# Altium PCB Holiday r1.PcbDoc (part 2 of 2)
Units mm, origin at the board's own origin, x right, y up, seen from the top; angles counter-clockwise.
Board outline 67 x 67 mm, 4 copper layers (Top Layer, Mid-Layer 1, InternalPlane1, Bottom Layer), stack 1.602 mm thick; 125 components, 139 nets, 622 pads, 401 vias.
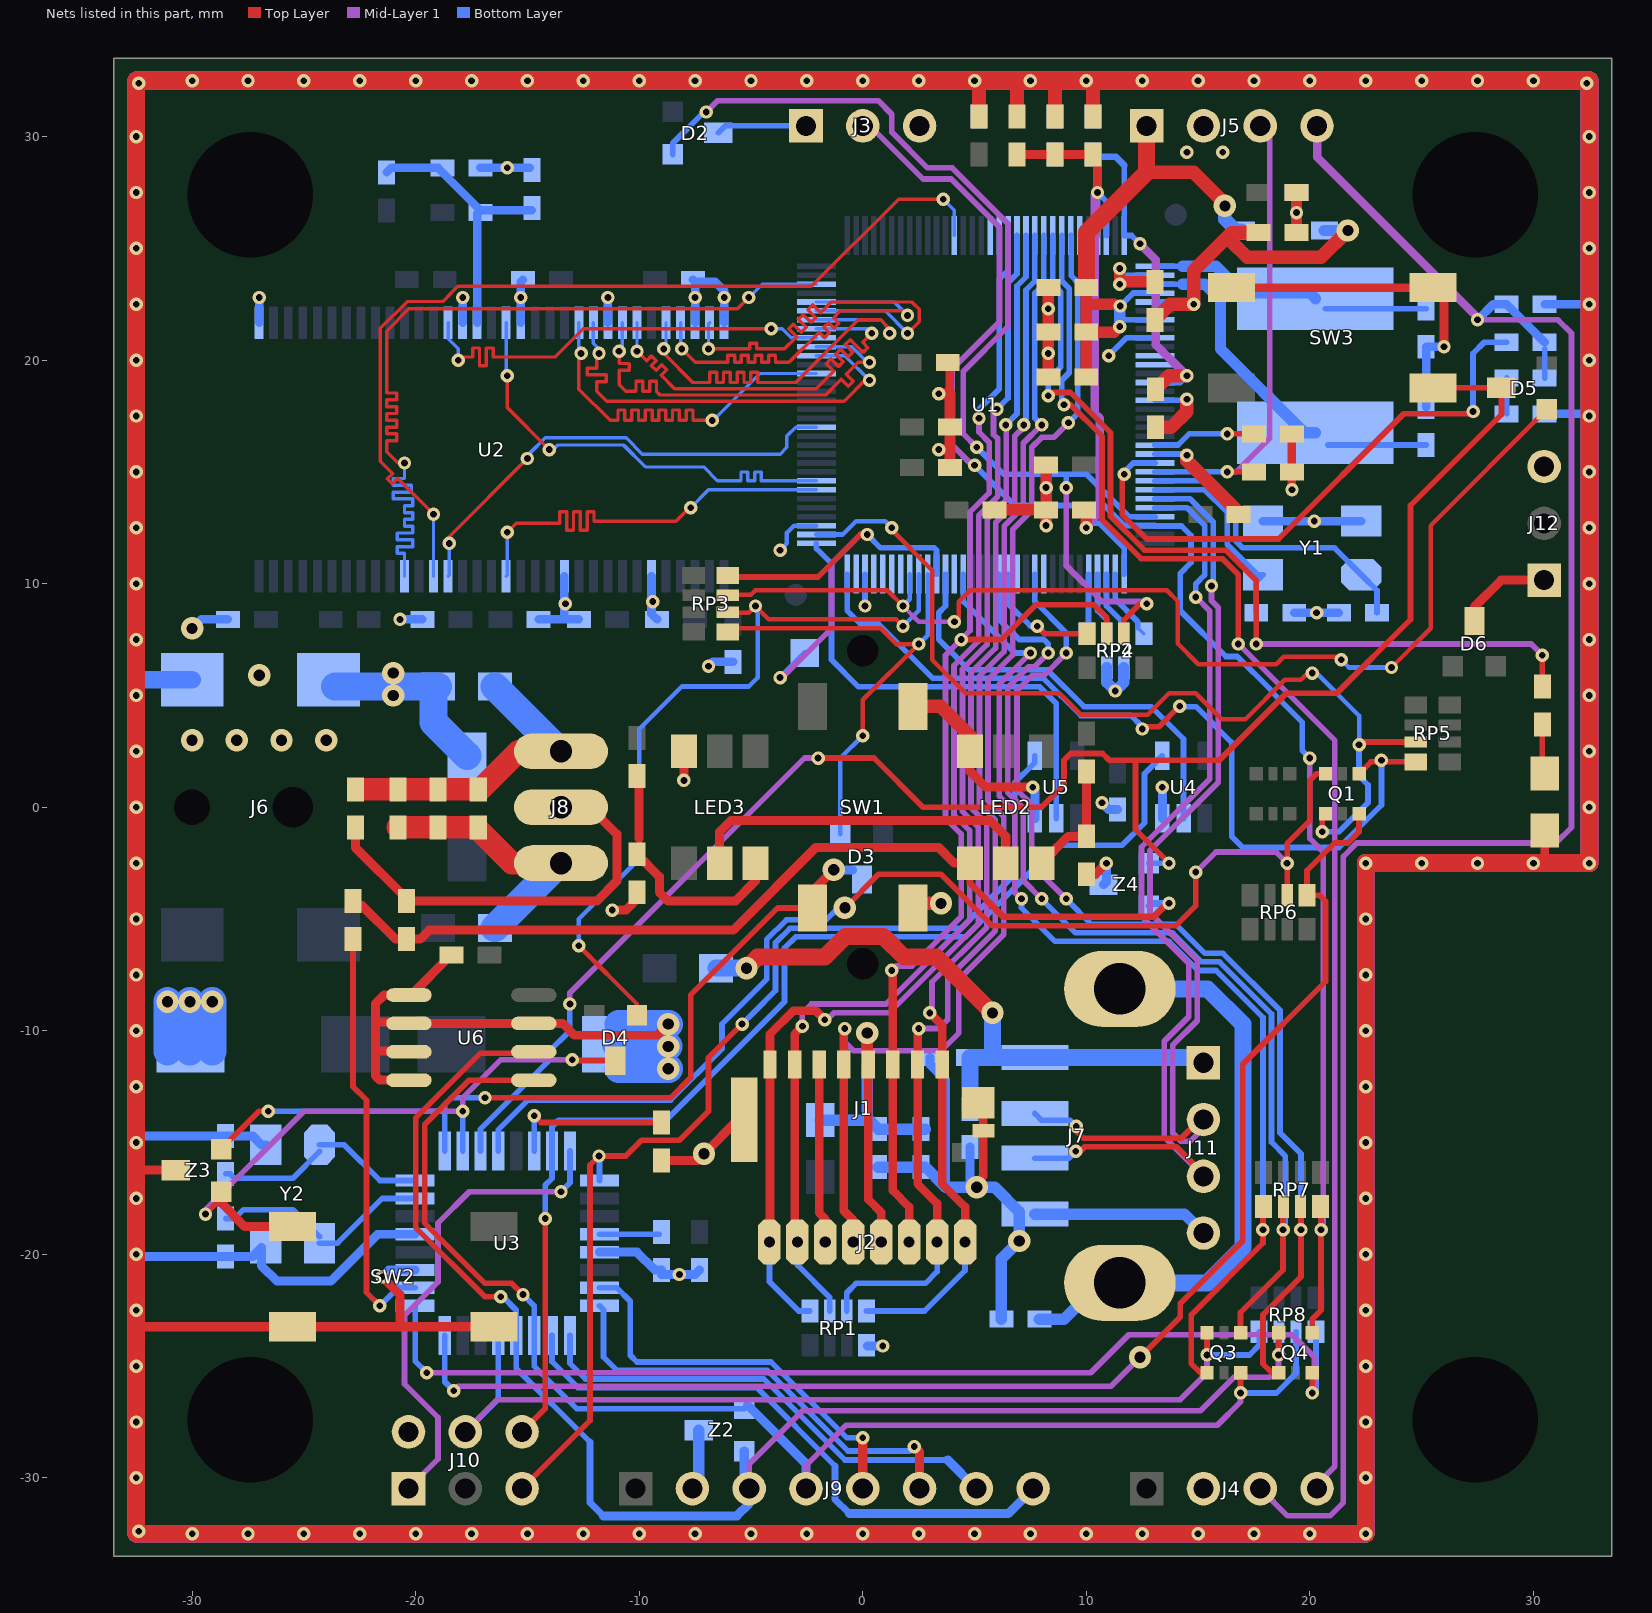
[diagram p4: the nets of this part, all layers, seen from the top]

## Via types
v1: diameter 0.6, hole 0.3, Top Layer to Bottom Layer, tented both sides, 365 vias
v2: diameter 1, hole 0.5, Top Layer to Bottom Layer, tented both sides, 33 vias
v3: diameter 0.6, hole 0.3, Top Layer to Bottom Layer, 2 vias
v4: diameter 0.9, hole 0.5, Top Layer to Bottom Layer, tented both sides, 1 vias

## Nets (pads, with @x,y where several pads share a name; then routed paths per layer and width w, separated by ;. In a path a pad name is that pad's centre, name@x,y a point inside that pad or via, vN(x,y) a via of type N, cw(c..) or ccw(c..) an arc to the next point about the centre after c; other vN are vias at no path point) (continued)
D9: U1.52 U2.56 | length 20.9
  Top Layer w0.152: v1(-12.6,20.3) -12.7,20.3 -12.7,18.7 -11.303,17.303 -10.948,17.303 -10.948,17.77 -10.643,17.77 -10.643,17.303 -10.338,17.303 -10.338,17.77 -10.033,17.77 -10.033,17.303 -9.728,17.303 -9.728,17.77 -9.424,17.77 -9.424,17.303 -9.119,17.303 -9.119,17.77 -8.814,17.77 -8.814,17.303 -8.509,17.303 -8.509,17.77 -8.204,17.77 -8.204,17.303 -7.9,17.303 -7.9,17.77 -7.595,17.77 -7.595,17.303 v1(-6.727,17.303)
  Bottom Layer w0.152: U2.56@-12.7,21.675 -12.7,20.5 -12.75,20.45 -12.8,20.4 -12.7,20.3 v1(-12.6,20.3) ; v1(-6.727,17.303) -6.697,17.303 -4.6,19.4 U1.52@-2.075,19.4
D10: U1.54 U2.57 | length 21
  Top Layer w0.152: v1(-11.8,20.3) -11.7,20.3 -11.75,20.25 -11.9,20.1 -11.9,19.643 -12.332,19.643 -12.332,19.338 -11.468,19.338 -11.468,19.033 -11.9,19.033 -11.9,18.6 -11.462,18.162 -0.838,18.162 v1@0.1,19.1
  Mid-Layer 1 w0.152: v1@0.1,19.1 v1(0.3,19.1)
  Bottom Layer w0.152: U2.57@-12.05,21.675 -12.05,20.75 -11.7,20.4 -11.7,20.3 -11.7,20.2 v1(-11.8,20.3) ; U1.54@-2.075,20.2 -0.8,20.2 v1(0.3,19.1)
D11: U1.55 U2.59 | length 20.9
  Top Layer w0.152: v1(-10.9,20.4) -10.9,19.848 -10.444,19.848 -10.444,19.543 -10.9,19.543 -10.9,18.9 -10.6,18.6 -10.143,18.6 -10.143,19.056 -9.838,19.056 -9.838,18.6 -9.533,18.6 -9.533,19.056 -9.228,19.056 -9.228,18.6 -9.07,18.441 -1.659,18.441 -0.954,19.146 -0.648,18.84 -0.433,19.055 -0.739,19.361 -0.2,19.9 v1(0.3,19.9)
  Bottom Layer w0.152: v1(-10.9,20.4) -10.75,20.55 U2.59@-10.75,21.675 ; U1.55@-2.075,20.6 -0.5,20.6 v1@0.15,19.95
D12: U1.57 U2.60 | length 20.9
  Top Layer w0.152: v1(-10.1,20.4) -9.67,19.97 -9.454,20.185 -9.239,19.97 -9.454,19.754 -9.239,19.539 -8.987,19.79 -8.772,19.575 -9.023,19.323 -8.421,18.721 -2.079,18.721 -1.301,19.499 -1.642,19.841 -1.427,20.056 -1.085,19.715 -0.87,19.93 -1.211,20.272 -0.996,20.487 -0.654,20.146 -0.439,20.361 -0.78,20.703 -0.565,20.918 -0.223,20.577 0.012,20.342 0.227,20.557 -0.008,20.792 v1(0.4,21.2)
  Bottom Layer w0.152: v1(-10.1,20.4) U2.60@-10.1,21.675 ; U1.57@-2.075,21.4 0.2,21.4 v1(0.4,21.2)
D13: U1.58 U2.62 | length 20.9
  Top Layer w0.152: v1(-8.9,20.5) -8.9,20.3 -7.6,19 -6.838,19 -6.838,19.451 -6.533,19.451 -6.533,19 -6.228,19 -6.228,19.451 -5.924,19.451 -5.924,19 -5.619,19 -5.619,19.451 -5.314,19.451 -5.314,19 -5.009,19 -5.009,19.451 -4.704,19.451 -4.704,19 -3,19 -0.2,21.8 0.8,21.8 1.104,21.496 1.104,21.2 v1(1.2,21.2)
  Bottom Layer w0.152: v1(-8.9,20.5) -8.8,20.6 U2.62@-8.8,21.675 ; U1.58@-2.075,21.8 0.8,21.8 1.104,21.496 1.104,21.2 v1(1.2,21.2)
D14: U1.60 U2.63 | length 20.9
  Top Layer w0.152: v1(-8.1,20.5) -7.5,19.9 -6.038,19.9 -6.038,20.221 -5.733,20.221 -5.733,19.9 -5.428,19.9 -5.428,20.221 -5.124,20.221 -5.124,19.9 -4.819,19.9 -4.819,20.221 -4.514,20.221 -4.514,19.9 -4.209,19.9 -4.209,20.221 -3.904,20.221 -3.904,19.9 -3.3,19.9 -1.954,21.246 -1.712,21.003 -1.496,21.219 -1.739,21.461 -1.523,21.677 -1.281,21.434 -1.065,21.65 -1.308,21.892 -1,22.2 1.8,22.2 v1(2,22)
  Bottom Layer w0.152: U2.63@-8.15,21.675 -8.15,20.5 -8.15,20.45 v1(-8.1,20.5) ; U1.60@-2.075,22.6 1.4,22.6 v1(2,22)
D15: U1.59 U2.65 | length 21.1
  Top Layer w0.152: v1(-6.9,20.5) -5.048,20.5 -5.048,20.754 -4.743,20.754 -4.743,20.5 -3.5,20.5 -2.961,21.039 -3.32,21.398 -3.105,21.614 -2.746,21.254 -2.53,21.47 -2.883,21.822 -2.667,22.038 -2.315,21.685 -2.099,21.901 -2.452,22.253 -2.236,22.469 -1.884,22.116 -1.4,22.6 2.2,22.6 2.525,22.275 2.525,21.725 v1(2,21.2) v1@1.9,21.3
  Bottom Layer w0.152: v1(-6.9,20.5) -6.9,21.625 U2.65@-6.85,21.675 ; U1.59@-2.075,22.2 1,22.2 v1(2,21.2)
D_RXD: D2.1 RP4.2.1 U1.125 | length 49.9
  Top Layer w0.254: v1@9,14.2 v1(9.1,14.3) ; RP4.2.1@11.681,7.762 11.681,8.381 12.4,9.1 v1(12.7,9.1)
  Mid-Layer 1 w0.254: v1(-7,31.1) -6.5,31.6 0.7,31.6 1.3,31 1.3,30.2 2.9,28.6 4,28.6 6.5,26.1 6.5,21.5 4.5,19.5 4.5,16.7 v1(5.1,16.1) ; v1(9.1,14.3) 9.1,10.8 10.7,9.2 12.6,9.2 v1(12.7,9.1)
  Bottom Layer w0.254: D2.1@-8.5,29.2 -8.5,29.7 -7.1,31.1 v1(-7,31.1) ; v1(5.1,16.1) 6.3,14.9 9.1,14.9 ; v1(9.1,14.3) 9.1,14.9 ; U1.125@13.075,13 11.9,13 10,14.9 9.1,14.9
D_TXD: J3.2 Q4.1 RP7.4.1 U1.126 | length 71
  Top Layer w0.254: Q4.1@20.1,-23.5 20.1,-22.9 20.5,-22.5 v1(20.5,-18.9) 20.5,-17.892 RP7.4.1@20.47,-17.862
  Mid-Layer 1 w0.254: J3.2@0,30.48 0.32,30.48 2.7,28.1 3.961,28.1 6.119,25.942 6.119,21.719 4,19.6 4,16.2 4.9,15.3 v1(5,15.3) ; v1(20,2.2) 20,-1.4 20.6,-2 20.6,-18.8 v1(20.5,-18.9)
  Bottom Layer w0.254: v1(5,15.3) 6.8,13.5 10.8,13.5 11.7,12.6 U1.126@13.075,12.6 13.094,12.581 14.258,12.581 14.681,12.158 14.681,10.942 14.199,10.46 14.199,8.788 16.241,6.746 16.754,6.746 18.281,5.219 18.281,5.181 19.654,3.807 19.654,2.546 v1(20,2.2)
D_TXD_5V: Q4.6 RP8.1.1 U3.1 | length 49.4
  Top Layer w0.254: v1(20.1,-26.2) Q4.6@20.1,-25.3
  Mid-Layer 1 w0.254: v1(-19.5,-25.3) 10.2,-25.3 11.9,-23.6 19.2,-23.6 20.2,-24.6 20.2,-26 v1@20.05,-26.15
  Bottom Layer w0.254: U3.1@-20.025,-22.3 -20.025,-24.775 v1(-19.5,-25.3) ; v1(20.1,-26.2) 20.27,-26.03 RP8.1.1@20.27,-23.462
DEBUG: J4.4 U1.89 | length 64
  Top Layer w0.254: v1(9,18) 9.3,18 10.7,16.6 10.7,12.861 12.442,11.119 16.081,11.119 16.8,10.4 v1(16.8,7.3)
  Mid-Layer 1 w0.254: v1(16.8,7.3) 21.119,2.981 21.119,-29.481 20.32,-30.28 J4.4@20.32,-30.48
  Bottom Layer w0.254: U1.89@8.9,25.575 8.9,23.539 9.235,23.204 9.235,19.435 8.9,19.1 8.9,18.1 v1(9,18)
DOUT: R9.2 U3.2 | length 18.8
  Top Layer w0.254: R9.2@-22.8,-5.9 -22.8,-12.5 -22.2,-13.1 -22.2,-21.7 v1(-21.6,-22.3)
  Bottom Layer w0.254: v1(-21.6,-22.3) -20.8,-21.5 U3.2@-20.025,-21.5
DOUT2: L6.1 LED2.1 R9.1 Z4.2 | length 41.7
  Top Layer w0.305: LED2.1@4.8,-2.5 4.8,-3.4 6.3,-4.9 13,-4.9 v1@13.6,-4.3
  Top Layer w0.406: R9.1@-22.8,-4.4 -22.4,-4.4 -20.9,-5.9 L6.1@-20.4,-5.9 -19.8,-5.9 -19.4,-5.5 -5.8,-5.5 -2.1,-1.8 3.4,-1.8 4.1,-2.5 LED2.1@4.8,-2.5
  Bottom Layer w0.305: Z4.2@12.8,-4.405 12.905,-4.3 v1(13.7,-4.3)
DQM0: U1.46 U2.20 | length 21
  Top Layer w0.152: v1(-18.5,11.8) -18.5,12.1 v1(-15,15.6)
  Bottom Layer w0.152: U2.20@-18.55,10.325 -18.5,10.375 v1(-18.5,11.8) ; v1@-14.931,15.8 -14.21,16.521 -10.579,16.521 -9.856,15.797 -3.692,15.797 -3.394,16.094 -3.394,16.606 -3,17 U1.46@-2.075,17
DQM1: U1.56 U2.47 | length 21
  Top Layer w0.152: v1@-18.1,20.141 -17.448,20.141 -17.448,20.541 -17.143,20.541 -17.143,19.742 -16.838,19.742 -16.838,20.541 -16.533,20.541 -16.533,20.141 -13.759,20.141 -12.5,21.4 v1(-4.1,21.4)
  Bottom Layer w0.152: U2.47@-18.55,21.675 -18.55,20.95 -18.1,20.5 v1(-18.1,20) ; v1(-4.1,21.4) -3.6,21.4 -3.2,21 U1.56@-2.075,21
DQS0: U1.39 U2.16 | length 21.2
  Top Layer w0.152: v1(-15.9,12.3) -15.5,12.7 -13.548,12.7 -13.548,13.216 -13.243,13.216 -13.243,12.384 -12.938,12.384 -12.938,13.216 -12.633,13.216 -12.633,12.384 -12.328,12.384 -12.328,13.216 -12.024,13.216 -12.024,12.8 -8.354,12.8 -7.727,13.427 v1@-7.624,13.53
  Mid-Layer 1 w0.152: v1(-7.7,13.4) -7.624,13.4 v1@-7.624,13.53
  Bottom Layer w0.152: U2.16@-15.95,10.325 -15.9,10.375 v1(-15.9,12.3) ; v1(-7.7,13.4) -6.9,14.2 U1.39@-2.075,14.2
DQS1: U1.40 U2.51 | length 20.9
  Top Layer w0.152: v1(-15.9,19.3) -15.9,17.881 v1(-14.019,16) v1@-13.838,16
  Bottom Layer w0.152: U2.51@-15.95,21.675 -15.95,19.35 v1(-15.9,19.3) ; v1(-14.019,16) -13.838,16 -13.635,16.203 -10.703,16.203 -9.721,15.221 -7.121,15.221 -6.5,14.6 -5.448,14.6 -5.448,14.994 -5.143,14.994 -5.143,14.6 -4.838,14.6 -4.838,14.994 -4.533,14.994 -4.533,14.6 U1.40@-2.075,14.6
GND: C1.2 C2.2 C3.2 C4.2 C5.2 C6.2 C7.2 C8.2 C9.2 C10.2 C11.2 C12.2 C13.2 C14.2 C15.2 C16.2 C17.2 C18.2 C19.2 C20.2 C21.2 C22.2 C23.2 C24.2 C25.2 C26.2 C27.2 C28.2 C29.2 C30.2 C31.2 C32.2 C33.2 C35.2 C36.2 C37.2 C38.2 C39.2 C40.2 C41.2 C42.2 C43.2 C44.2 C45.2 C46.2 C48.2 C49.1 C50.2 C51.2 C55.1 C56.1 C57.2 J1.6 J1.G1 J1.G2 J1.G3 J2.6 J3.3 J4.2 J5.2 J6.2 J6.3 J7.4 J9.2 J10.6 J11.4 J12.3 L4.1 L7.1 LED1.K LED2.6 LED3.6 pad.0@27.4,27.4 pad.0@-27.4,27.4 pad.0@-27.4,-27.4 R5.2 R7.1 R12.1 RP1.4.2 RP2.2.2 RP2.3.2 SW1.3 SW1.4 SW2.3 SW2.4 SW3.3 SW3.4 U1.30 U1.35 U1.98 U1.105 U1.112 U1.118 U2.6 U2.12 U2.34 U2.48 U2.52 U2.58 U2.64 U2.66 U3.3 U3.5 U3.21 U4.3 U5.3 U6.1 U6.2 U6.3 U6.4 U6.7 Y1.3 Y1.4 Y2.3 Y2.4 Z1.1 Z2.3 Z3.3 Z4.3 | length 1042.6
  Top Layer w0.254: v1(11.5,23.4) v1@11.6,23.5
  Top Layer w0.381: J1.6@-1.95,-11.5 -1.95,-18.15 -1.675,-18.425 ; 3.9,18.5 C6.2@3.9,20 ; v2(5.1,-17) 5.1,-16.8 5.4,-16.5 J1.G3@5.4,-14.475 5.4,-13.45 J1.G2@5.175,-13.225 ; SW3.4@16.49,23.24 SW3.3@25.51,23.24 26,22.75 v1(26,20.6) ; v1(19.2,14.2) C31.2@19.2,15 C37.2@19.2,16.7 ; 30.5,-2.5 LED1.K@30.5,-1.04
  Top Layer w0.4: v1(-21.5,-21) -20.7,-21.8 -20.7,-23.24 ; U6.2@-20.37,-9.6 U6.2@-20.3,-9.67 U6.7@-14.712,-9.67 -13.43,-9.67 -12.9,-10.2 -9.2,-10.2 v2(-8.7,-9.7)
  Top Layer w0.406: -32.5,-16.3 -32.435,-16.235 Z3.3@-30.732,-16.235 ; -32.44,-23.24 SW2.3@-25.51,-23.24 -20.7,-23.24 SW2.4@-16.49,-23.24 ; U6.2@-20.37,-9.6 -21.8,-9.6 ; U6.3@-20.34,-10.9 -21.8,-10.9 ; U6.4@-20.3,-12.21 -20.31,-12.2 -21.6,-12.2 -21.8,-12 -21.8,-10.9 ; C57.2@-18.4,-6.6 -20.2,-8.4 U6.1@-20.3,-8.4 -21.4,-8.4 -21.8,-8.8 -21.8,-9.6 ; v1(-11.2,-4.6) -10.6,-4.6 -10.1,-4.1 C49.1@-10.1,-3.8 ; R12.1@-9,-15.8 -7.4,-15.8 v2(-7.1,-15.5) -5.58,-13.98 J1.G1@-5.3,-13.98 ; v1(-8,1.2) LED3.6@-8,2.5 ; LED2.6@4.8,2.5 4.8,1.6 5.5,0.9 v1(7.6,0.9) ; C55.1@10,-3 10.4,-3 v1(10.9,-2.5) ; -21.8,-10.9 -21.8,-9.6
  Top Layer w0.508: v1(3.4,16) 3.9,16 ; v1(3.4,18.5) 3.9,18.5 C32.2@3.9,17 3.9,16 ; C5.2@3.9,15.2 3.9,16 ; C3.2@5.9,13.3 C1.2@8.2,13.3 ; v1@8.2,12.6 C1.2@8.2,13.3 ; v1@8.2,14.3 C1.2@8.2,13.3 ; v1@8.2,14.3 C7.2@8.2,15.3 ; C20.2@8.3,19.25 C19.2@8.3,21.25 C18.2@8.3,23.25 ; v1(11.5,23.4) v1(11.5,24.1) ; v1@11.6,23.5 C8.2@13.075,23.5 ; C9.2@19.4,25.7 v1(19.4,26.6) C13.2@19.4,27.5
  Top Layer w0.61: SW1.3@2.24,-4.51 2.49,-4.51 2.7,-4.3 v2(3.5,-4.3) ; SW1.4@2.24,4.51 3.49,4.51 4.8,3.2 LED2.6@4.8,2.5 ; C4.2@5.2,30.9 v1@5.2,32.4 ; C2.2@6.9,30.9 6.9,32.4 ; C11.2@8.6,30.9 8.6,32.5 ; C12.2@10.3,30.9 10.3,32.5 ; C38.2@13.1,17 13.8,17 14.5,17.7 v1(14.5,18.25) ; v1(14.5,15.75) 14.5,15.5 C10.2@16.85,13.15
  Top Layer w0.8: v1@32.385,-2.5 v1(22.5,-2.5) v1(22.5,-32.5) -32.5,-32.5 -32.5,32.5 32.5,32.5 v1(32.5,-2.5)
  Mid-Layer 1 w0.8: v1@-32.5,-32.5 v1(22.5,-32.5) v1(22.5,-2.5) v1(32.5,-2.5) 32.5,32.5 -32.5,32.5 v1@-32.5,-32.5
  Bottom Layer w0.203: v1(-3.7,11.5) -3.4,11.8 -3.4,12.269 -3.069,12.6 U1.35@-2.075,12.6
  Bottom Layer w0.254: v1(0.1,9) U1.30@0.1,10.425 ; v1(11,20.2) 11.8,21 U1.105@13.075,21 ; v1(11.5,24.1) 11.5,23.8 U1.98@13.075,23.8 ; U1.118@13.075,15.8 14.45,15.8 v1(14.5,15.75) ; U1.112@13.075,18.2 14.45,18.2 v1(14.5,18.25)
  Bottom Layer w0.381: v2(-30,8) -29.6,8.4 C27.2@-28.4,8.4 ; U2.34@-27,21.675 v1(-27,22.8) ; v1(-20.7,8.4) C26.2@-19.7,8.4 ; U2.48@-17.9,21.675 v1(-17.9,22.8) ; R5.2@-17.1,28.6 C36.2@-14.9,28.6 ; U2.52@-15.3,21.675 -15.3,23.5 C28.2@-15.2,23.6 ; U2.12@-13.35,10.325 -13.35,8.4 C25.2@-14.5,8.4 C24.2@-12.7,8.4 ; U2.58@-11.4,21.675 v1(-11.4,22.8) ; U2.6@-9.45,10.325 -9.45,8.65 C23.2@-9.2,8.4 ; C29.2@-7.6,23.6 C29.2@-7.5,23.5 ; U2.64@-7.5,21.675 C29.2@-7.5,23.5 ; v1(-6.9,6.3) -6.7,6.5 C22.2@-5.8,6.5 ; U2.66@-6.2,21.675 -6.2,23.1 -6.6,23.5 C29.2@-7.5,23.5 ; RP1.4.2@0.208,-24.1 v1(0.9,-24.1) ; Y1.3@17.9,12.8 v1(20.2,12.8) Y1.4@22.3,12.8 ; C33.2@19.3,8.7 v1(20.3,8.7) C35.2@21.3,8.7 ; v1@19.4,26.6 C14.2@19.4,27.5 ; C30.2@25.2,17.9 C21.2@25.2,20.6 v1(26,20.6) ; C41.2@30.5,17.6 v1@32.4,17.6 ; R7.1@30.5,22.5 v1(32.5,22.5)
  Bottom Layer w0.4: Y2.3@-26.9,-19.7 -26.9,-20.5 -26.2,-21.2 -23.8,-21.2 -21.7,-19.1 U3.5@-20.025,-19.1 ; v1(-21.5,-21) -21.2,-20.7 U3.3@-20.025,-20.7 ; U3.21@-11.775,-19.9 -10.1,-19.9 -9.3,-20.7 C44.2@-9,-20.7 -9,-20.9 v1(-8.2,-20.9) -7.5,-20.9 C48.2@-7.3,-20.7
  Bottom Layer w0.406: v1@-32.4,-20.1 C43.2@-28.5,-20.1 -27.3,-20.1 Y2.3@-26.9,-19.7 ; -32.3,-14.7 C42.2@-28.5,-14.7 -27.3,-14.7 -26.9,-15.1 Y2.4@-26.7,-15.1 ; C46.2@3,-11.2 3,-11.5 3.7,-12.2 3.7,-17 ; v2@4.8,-16.7 C45.2@4.8,-15.2 ; v1(7.6,0.9) 7.7,0.8 U5.3@7.7,-0.5 ; v1(10.7,0.2) 11,-0.1 C56.1@11.4,-0.1 ; Z4.3@10.768,-3.465 10.9,-3.333 v1(10.9,-2.5) ; U4.3@13.4,-0.5 v1(13.4,0.9)
  Bottom Layer w0.508: J9.2@-7.62,-30.48 -7.332,-30.192 Z2.3@-7.332,-27.865 ; C39.2@0.7,-16.1 C40.2@2.6,-16.1 2.8,-16.1 3.7,-17 v2(5.1,-17) 5.9,-17 7,-18.1 v2(7,-19.4) 7,-19.6 6.8,-19.6 6.2,-20.2 L4.1@6.2,-22.9 ; J7.4@7.7,-18.2 14.39,-18.2 J11.4@15.24,-19.05 ; RP2.2.2@10.919,6.238 10.919,5.581 v1(11.3,5.2) 11.681,5.581 RP2.3.2@11.681,6.238
  Bottom Layer w0.61: C15.2@5.2,30.9 v1@5.2,32.3 ; C16.2@8.6,30.9 8.6,32.5 ; C17.2@10.3,30.9 10.3,32.5
  Bottom Layer w0.8: -32.4,5.7 J6.2@-30,5.7 ; v1@-32.5,-32.5 v1(22.5,-32.5) v1(22.5,-2.5) v1(32.5,-2.5) 32.5,32.5 -32.5,32.5 v1@-32.5,-32.5
  Bottom Layer w1.27: C50.2@-31.1,-10.917 v2(-31.1,-8.7) v2@-31.1,-8.683 ; C50.2@-30.1,-10.917 v2(-30.1,-8.7) v2@-30.1,-8.683 ; C50.2@-29.1,-10.917 v2(-29.1,-8.7) v2@-29.1,-8.683 ; J6.3@-23.6,5.4 L7.1@-19,5.4 ; L7.1@-19.2,5.2 -19.2,3.8 Z1.1@-17.7,2.3 ; C51.2@-11.034,-10.6 -10.934,-10.7 v2(-8.7,-10.7) ; C51.2@-10.917,-11.7 v2@-8.683,-11.7 ; C51.2@-10.917,-9.7 v2(-8.7,-9.7) v2@-8.683,-9.7
  other v1: -30,-32.5 -27.5,-32.5 -25,-32.5 -22.5,-32.5 -20,-32.5 -17.5,-32.5 -15,-32.5 -12.5,-32.5 -10,-32.5 -7.5,-32.5 -5,-32.5 -2.5,-32.5 0,-32.5 2.5,-32.5 5,-32.5 7.5,-32.5 10,-32.5 12.5,-32.5 15,-32.5 17.5,-32.5 20,-32.5 -32.385,-32.385 -32.5,-30 22.5,-30 -32.5,-27.5 22.5,-27.5 -32.5,-25 22.5,-25 -32.5,-22.5 22.5,-22.5 -32.5,-20 22.5,-20 -32.5,-17.5 22.5,-17.5 -32.5,-15 22.5,-15 -32.5,-12.5 22.5,-12.5 -32.5,-10 22.5,-10 -32.5,-7.5 22.5,-7.5 -32.5,-5 22.5,-5 -32.5,-2.5 25,-2.5 27.5,-2.5 30,-2.5 -32.5,0 32.5,0 -32.5,2.5 32.5,2.5 -32.5,5 32.5,5 -32.5,7.5 32.5,7.5 -13.3,9.1 -9.4,9.2 -32.5,10 32.5,10 -32.5,12.5 32.5,12.5 8.2,12.6 8.2,14.3 -32.5,15 32.5,15 -32.5,17.5 32.5,17.5 -32.5,20 32.5,20 8.3,20.3 8.3,22.3 -32.5,22.5 -15.3,22.8 -7.5,22.8 -6.2,22.8 -32.5,25 32.5,25 -32.5,27.5 32.5,27.5 -15.9,28.6 14.5,29.3 16.1,29.3 -32.5,30 32.5,30 -32.385,32.385 32.385,32.385 -30,32.5 -27.5,32.5 -25,32.5 -22.5,32.5 -20,32.5 -17.5,32.5 -15,32.5 -12.5,32.5 -10,32.5 -7.5,32.5 -5,32.5 -2.5,32.5 0,32.5 2.5,32.5 5,32.5 7.5,32.5 10,32.5 12.5,32.5 15,32.5 17.5,32.5 20,32.5 22.5,32.5 25,32.5 27.5,32.5 30,32.5
  other v2: -8.7,-11.7 -30,3 -28,3 -26,3 -24,3 -21,5 -27,5.9 -21,6
GPIO1: D3.1 RP3.1.1 U1.23 | length 21.8
  Top Layer w0.203: RP3.1.1@-5.738,8 0.8,8 1.5,7.3 v1(2.5,7.3) 0,4.8 v1(0,3.2)
  Bottom Layer w0.203: D3.1@-1,-1.2 -1,2.2 v1(0,3.2) ; v1(2.5,7.3) 2.9,7.7 U1.23@2.9,10.425
GPIO2: D4.1 RP3.2.1 U1.24 | length 35
  Top Layer w0.203: v1(-12.7,-6.2) -10.1,-8.8 D4.1@-10.1,-9.3 ; RP3.2.1@-5.657,8.7 -5.1,8.7 v1(-4.8,9) -4.2,8.4 1.5,8.4 v1(1.8,8.1)
  Bottom Layer w0.203: v1(-12.7,-6.2) -12.7,-5 -10,-2.3 -10,3.5 -8.1,5.4 -5.1,5.4 -4.7,5.8 v1@-4.7,9 ; v1(1.8,8.1) 2.5,8.8 U1.24@2.5,10.425
GPIO3: D5.1 RP3.3.1 U1.25 | length 49.8
  Top Layer w0.203: RP3.3.1@-5.719,9.5 -5,9.5 -4.8,9.7 1.1,9.7 v1(1.8,9) ; v1(4.1,8.3) 4.3,8.5 4.3,9.2 4.8,9.7 13.6,9.7 14.1,9.2 14.1,7.312 15.012,6.4 18.5,6.4 18.829,6.729 21.271,6.729 v1(21.4,6.6) ; v1(23.65,6.25) 25.4,8 25.4,12.6 D5.1@30.6,17.8
  Mid-Layer 1 w0.203: v1(1.8,9) 2.5,8.3 v1(4.1,8.3)
  Bottom Layer w0.203: v1(1.8,9) 2.1,9.3 U1.25@2.1,10.425 ; v1(21.4,6.6) 21.75,6.25 v1(23.65,6.25)
GPIO4: U1.27
GPIO5: U1.26
GPIO6: U1.29
GPIO7: U1.28
GPIO16: Q3.4 RP7.1.1 U1.19 | length 49.1
  Top Layer w0.254: Q3.4@15.4,-25.3 15.1,-25.3 14.7,-24.9 14.7,-22.7 17.9,-19.5 v1(17.9,-18.9) 17.9,-17.892 RP7.1.1@17.93,-17.862
  Mid-Layer 1 w0.254: v1(7.1,-4.1) 6.8,-3.8 6.8,-0.2 6.1,0.5 6.1,5.5 v1(7.5,6.9)
  Bottom Layer w0.254: U1.19@4.5,10.425 4.5,9.2 6.8,6.9 v1(7.5,6.9) ; v1(7.1,-4.1) 7.1,-4.5 8.6,-6 13.7,-6 15,-7.3 15.8,-7.3 17.9,-9.4 v1(17.9,-18.9)
GPIO17: U1.20
GPIO23: Q1.4 RP5.3.1 U1.34 | length 43.5
  Top Layer w0.203: v1@1.25,12.45 3.1,10.6 3.1,6.6 4.6,5.1 8.8,5.1 9.755,4.145 12.744,4.145 13.074,4.474 13.7,5.1 14.9,5.1 16.063,3.937 17.12,3.937 18.883,5.7 19.6,5.7 20.1,6.2 v1(20.1,6)
  Top Layer w0.254: v1(20.554,-1.1) 20.554,-0.446 Q1.4@20.7,-0.3 ; v1(22.2,2.8) 22.319,2.919 RP5.3.1@24.738,2.919
  Bottom Layer w0.203: U1.34@-2.075,12.2 -0.9,12.2 -0.3,12.8 1,12.8 v1(1.3,12.5) ; v1@20.1,6.2 22.2,4.1 v1(22.2,2.8)
  Bottom Layer w0.254: v1(20.554,-1.1) 21.3,-1.1 22.6,0.2 22.6,1 22.2,1.4 v1(22.2,2.8)
GPIO23_5V: Q1.3 RP6.2.1 U3.12 | length 52.4
  Top Layer w0.254: v2(-0.8,-4.5) 0.7,-3 3.5,-3 5.807,-5.306 13.994,-5.306 14.9,-4.4 v1(14.9,-2.9) ; RP6.2.1@18.981,-3.938 v1(18.981,-2.5) 18.981,-1.619 20,-0.6 20,1.2 20.3,1.5 Q1.3@20.7,1.5
  Mid-Layer 1 w0.254: v1(14.9,-2.9) 15.8,-2 18.481,-2 v1(18.981,-2.5)
  Bottom Layer w0.254: U3.12@-16.3,-15.375 -16.3,-14.422 -14.978,-13.1 -8.6,-13.1 -6.3,-10.8 -6.3,-9.7 -4.3,-7.7 -4.3,-5.922 -3.416,-5.038 -1.638,-5.038 -1.1,-4.5 v2(-0.8,-4.5)
GPIO25: U1.31
GPIO52: U1.13
GPIO53: U1.10
GPIO60: U1.91
GPIO65: R1.2 U1.88 | length 40.1
  Top Layer w0.254: v1(8.3,18.4) 8.3,18.3 8.554,18.554 9.285,18.554 11.081,16.758 11.081,13.019 12.6,11.5 16.239,11.5 17.6,10.139 v1(17.6,7.3) ; R1.2@30.4,5.4 v1(30.4,6.8)
  Mid-Layer 1 w0.254: v1(17.6,7.3) 29.9,7.3 v1(30.4,6.8)
  Bottom Layer w0.254: v1@8.3,18.3 v1(8.3,18.4) ; v1@8.3,18.408 8.3,19.139 8.854,19.693 8.854,23.046 8.5,23.4 U1.88@8.5,25.575
GPIO91: U1.81
GPIO92: U1.82
LCD_D00: RP2.4.1 U1.2 | length 3.2
  Bottom Layer w0.152: RP2.4.1@12.3,8.032 RP2.4.1@12.57,7.762
  Bottom Layer w0.254: U1.2@11.3,10.425 11.3,9.3 12.3,8.3 RP2.4.1@12.3,8.032
LCD_D01: RP2.3.1 U1.3 | length 3
  Bottom Layer w0.254: U1.3@10.9,10.425 10.9,9 11.681,8.219 RP2.3.1@11.681,7.762
LCD_D02: RP2.2.1 U1.4 | length 2.8
  Bottom Layer w0.254: U1.4@10.5,10.425 10.5,8.8 10.919,8.381 RP2.2.1@10.919,7.762
LCD_D03: RP2.1.1 U1.5 | length 2.7
  Bottom Layer w0.152: RP2.1.1@10.03,7.762 RP2.1.1@10.1,7.832
  Bottom Layer w0.254: RP2.1.1@10.1,7.832 U1.5@10.1,10.425
LCD_RS: RP4.4.1 U1.14 | length 5.4
  Top Layer w0.254: v1(7.8,8.1) 8.138,7.762 RP4.4.1@10.03,7.762
  Bottom Layer w0.254: U1.14@6.5,10.425 6.5,9.1 7.5,8.1 v1(7.8,8.1)
LRADC0: U1.108
LRADC1: U1.107
MISO: RP3.4.1 TP1.1 U1.22 | length 21.5
  Top Layer w0.254: RP3.4.1@-6.038,10.37 -5.968,10.3 -2,10.3 -0.1,12.2 v1(0.2,12.2)
  Mid-Layer 1 w0.254: v1@-3.7,5.7 -1.4,8 -1.4,10.9 -0.1,12.2 v1(0.2,12.2)
  Bottom Layer w0.254: v1@-3.7,5.7 v1(-3.7,5.8) TP1.1@-2.6,6.9 ; v1(0.2,12.2) 0.8,11.6 3.2,11.6 3.3,11.5 U1.22@3.3,10.425
MISO_5V: J10.1 U3.16 | length 22
  Mid-Layer 1 w0.254: J10.1@-20.32,-30.48 -19,-29.16 -19,-27.3 -20.5,-25.8 -20.5,-22.74 -19,-21.24 -19,-18.6 -17.6,-17.2 v1(-13.5,-17.2)
  Bottom Layer w0.254: J10.1@-20.32,-30.48 J10.1@-20.32,-30.22 ; v1(-13.5,-17.2) -13.1,-16.8 U3.16@-13.1,-15.375
MOSI: U1.21 U4.2 | length 19.4
  Bottom Layer w0.254: U1.21@3.7,10.425 3.7,9 3.4,8.7 3.4,7.5 3.7,7.2 4.754,6.146 8.254,6.146 9.9,4.5 12.9,4.5 14.35,3.05 U4.2@14.35,-0.5
MOSI_5V: J10.4 U3.15 U4.4 | length 51.1
  Top Layer w0.254: J10.4@-15.24,-27.94 -14.2,-26.9 v1(-14.2,-18.4)
  Bottom Layer w0.254: v1(-14.2,-18.4) -14.2,-16.9 -13.9,-16.6 U3.15@-13.9,-15.375 -13.9,-14.3 -13.6,-14 -8.8,-14 -3.5,-8.7 -3.5,-6.3 -3,-5.8 4.6,-5.8 8.7,-1.7 11.6,-1.7 12.6,-0.7 12.6,1.5 U4.4@13.4,2.3
NetC21_1: C21.1 L1.1 U1.97 | length 12
  Bottom Layer w0.254: U1.97@13.325,24.2 14.3,24.2 ; L1.1@20.7,22.3 C21.1@25.2,22.3
  Bottom Layer w0.508: 14.3,24.2 15.8,24.2 17,23 20,23 L1.1@20.25,22.75
NetC30_1: C30.1 L1.2 U1.99 | length 15.5
  Bottom Layer w0.254: U1.99@13.175,23.4 14.3,23.4 ; L1.2@20.8,16.2 C30.1@25.2,16.2
  Bottom Layer w0.508: 14.3,23.4 15.3,23.4 16,22.7 16,20.5 19.75,16.75 L1.2@20.25,16.75
NetC33_1: C33.1 U1.122 Y1.2 | length 9.1
  Bottom Layer w0.254: U1.122@13.075,14.2 15.3,14.2 16.3,13.2 16.3,11.761 17.661,10.4 Y1.2@17.9,10.4 17.6,10.1 C33.1@17.6,8.7
NetC34_2: C34.2 C36.1 R4.1 R5.1 U2.49 | length 12.5
  Bottom Layer w0.381: R4.1@-21.3,28.4 -21.1,28.6 -19,28.6 C34.2@-17.1,26.7 ; U2.49@-17.25,21.675 -17.25,26.551 C34.2@-17.1,26.7 ; C36.1@-14.8,26.7 C34.2@-17.1,26.7
NetC35_1: C35.1 U1.121 Y1.1 | length 13.8
  Bottom Layer w0.254: U1.121@13.075,14.6 15.439,14.6 16.681,13.358 16.681,11.919 17,11.6 21.1,11.6 Y1.1@22.3,10.4 23,9.7 C35.1@23,8.7
NetC37_1: C37.1 U1.117 | length 4.6
  Top Layer w0.254: v1(16.3,16.7) C37.1@17.5,16.7
  Bottom Layer w0.254: U1.117@13.075,16.2 14.1,16.2 14.6,16.7 v1(16.3,16.7)
NetC41_1: C41.1 R6.1 | length 1.6
  Bottom Layer w0.254: C41.1@28.8,17.6 R6.1@28.8,19.2
NetC42_1: C42.1 U3.8 Y2.1 | length 9.7
  Bottom Layer w0.254: C42.1@-28.5,-16.4 -28.3,-16.4 -28.1,-16.6 -25.5,-16.6 Y2.1@-24.3,-15.4 ; Y2.1@-24.3,-15.1 -23.2,-15.1 -21.6,-16.7 U3.8@-20.025,-16.7
NetC43_1: C43.1 U3.7 Y2.2 | length 10
  Bottom Layer w0.254: C43.1@-28.5,-18.4 -28.1,-18.4 -27.7,-18 -25.5,-18 Y2.2@-24.3,-19.2 ; Y2.2@-24.3,-19.5 -23.5,-19.5 -21.5,-17.5 U3.7@-20.025,-17.5
NetC44_1: C44.1 U3.20 | length 2.7
  Bottom Layer w0.254: U3.20@-11.775,-19.1 C44.1@-9.1,-19.1
NetC45_1: C45.1 C46.1 J7.1 J11.1 L3.2 | length 29.1
  Top Layer w0.762: v2(-5.2,-7.2) -4.7,-6.7 -1.7,-6.7 -0.792,-5.792 0.935,-5.792 1.843,-6.7 3.3,-6.7 v2(5.8,-9.2)
  Bottom Layer w0.762: L3.2@-6.56,-7.2 v2(-5.2,-7.2) ; C45.1@4.8,-13.5 C46.1@4.8,-11.3 ; C46.1@4.8,-11.2 5.8,-11.2 ; v2(5.8,-9.2) 5.8,-11.2 ; J11.1@15.24,-11.43 15.01,-11.2 J7.1@7.7,-11.2 5.8,-11.2
NetC47_1: C47.1 C52.2 C53.2 C54.1 J8.3 L7.2 | length 13.9
  Top Layer w1.016: C54.1@-22.5,0.8 -17.6,0.8 ; -17.6,0.8 C47.1@-17.2,0.8 -17.1,0.8 -15.4,2.5 J8.3@-13.5,2.5
  Bottom Layer w1.27: L7.2@-16.46,5.4 -13.56,2.5 J8.3@-13.5,2.5
NetC47_2: C47.2 C52.1 C53.1 J8.1 L5.2 | length 12.1
  Top Layer w1.016: C53.1@-20.8,-0.9 -17.3,-0.9 -15.7,-2.5 J8.1@-13.5,-2.5
  Bottom Layer w1.27: L5.2@-16.46,-5.4 -13.56,-2.5 J8.1@-13.5,-2.5
NetC49_2: C49.2 LED3.3 R10.1 | length 10.6
  Top Layer w0.406: C49.2@-10.1,-2.1 -9.1,-3.1 -9.1,-3.8 -8.7,-4.2 -5.7,-4.2 -4.8,-3.3 LED3.3@-4.8,-2.5 ; R10.1@-10.1,1.4 -10,1.3 -10,-1.4
NetC54_2: C54.2 J8.2 L6.2 | length 19.1
  Top Layer w0.406: C54.2@-22.7,-0.9 -22.7,-1.8 -20.4,-4.1 L6.2@-20.4,-4.2 -11.9,-4.2 -11,-3.3 -11,-1.2 -12.2,0 J8.2@-13.5,0
NetC55_2: C55.2 LED2.3 R11.1 | length 5.4
  Top Layer w0.406: LED2.3@8,-2.5 9.2,-1.3 C55.2@10,-1.3 R11.1@10,1.6
NetD2_2: D2.3 J3.1 | length 4.7
  Top Layer w0.254: J3.1@-2.54,30.48 J3.1@-1.92,30.48
  Bottom Layer w0.254: D2.3@-6.468,30.165 -6.153,30.48 J3.1@-2.54,30.48
NetD6_2: D6.3 J12.1 | length 4.2
  Top Layer w0.406: D6.3@27.365,8.332 27.365,8.965 28.56,10.16 J12.1@30.48,10.16
NetJ7_G1: J7.G1 J7.G2 L4.2 | length 26.6
  Bottom Layer w0.508: L4.2@7.9,-22.9 9,-22.9 10.625,-21.275 J7.G2@11.5,-21.275
  Bottom Layer w0.762: J7.G2@11.5,-21.275 15.425,-21.275 17,-19.7 17,-9.7 15.425,-8.125 J7.G1@11.5,-8.125
NetJ9_5: J9.5 U3.23 | length 18.2
  Top Layer w0.406: J9.5@0,-30.48 v1(0,-28.2)
  Bottom Layer w0.254: U3.23@-11.775,-21.5 -11,-21.5 -10.4,-22.1 -10.4,-24.514 -10.1,-24.814 -4.108,-24.814 -0.722,-28.2 v1(0,-28.2)
NetJ9_6: J9.6 U3.24 | length 20.1
  Top Layer w0.406: v1(2.3,-28.6) 2.54,-28.84 J9.6@2.54,-30.48
  Bottom Layer w0.254: U3.24@-11.775,-22.3 -11.6,-22.475 -11.6,-24.595 -11,-25.195 -4.266,-25.195 -0.661,-28.8 2.1,-28.8 v1(2.3,-28.6)
NetJ9_7: J9.7 U3.25 | length 21.8
  Bottom Layer w0.254: U3.25@-13.1,-23.625 -13.1,-24.876 -12.4,-25.576 -4.424,-25.576 -0.8,-29.2 3.8,-29.2
  Bottom Layer w0.406: 3.8,-29.2 J9.7@5.08,-30.48
NetJ9_8: J9.8 U3.26 | length 26.9
  Bottom Layer w0.254: U3.26@-13.9,-23.625 -13.9,-24.8 -12.743,-25.957 -4.743,-25.957 -1.239,-29.461
  Bottom Layer w0.305: -1.239,-29.461 -1.239,-30.961 -0.6,-31.6
  Bottom Layer w0.406: -0.6,-31.6 6.5,-31.6 J9.8@7.62,-30.48
NetLED1_A: LED1.A R1.1 | length 2.2
  Top Layer w0.254: R1.1@30.4,3.7 30.4,1.6 LED1.A@30.5,1.5
NetLED2_2: LED2.2 LED3.2 | length 15.9
  Top Layer w0.406: LED3.2@-6.4,-2.5 -6.4,-1.1 -5.9,-0.6 5.7,-0.6 6.4,-1.3 LED2.2@6.4,-2.5
NetR8_1: R8.1 U1.119 | length 26.6
  Top Layer w0.254: v1@11.6,14.9 11.6,13.1 12.7,12 18.6,12 24.2,17.6 v1@27.3,17.6
  Mid-Layer 1 w0.254: v1@11.6,14.9 v1(11.7,14.9) ; v1@27.3,17.6 v1(27.3,17.7)
  Bottom Layer w0.254: v1(11.7,14.9) 11.6,14.9 12.1,15.4 U1.119@13.075,15.4 ; v1(27.3,17.7) 27.3,20.3 27.8,20.8 R8.1@28.8,20.8
NetR12_2: R12.2 U3.14 | length 7.4
  Top Layer w0.254: v1(-14.7,-13.8) -14.4,-14.1 R12.2@-9,-14.1
  Bottom Layer w0.254: U3.14@-14.7,-15.375 v1(-14.7,-13.8)
PB1_5V: D3.3 SW1.1 U3.9 Z3.2 | length 38
  Top Layer w0.254: Z3.2@-28.7,-15.295 -27.005,-13.6 v1(-26.6,-13.6) ; v1(-16.9,-13) -8.6,-13 -7.7,-12.1 -7.7,-8.4 -3.81,-4.51 SW1.1@-2.24,-4.51
  Top Layer w0.406: SW1.1@-2.24,-4.51 -2.24,-3.74 v2(-1.3,-2.8)
  Bottom Layer w0.254: v1(-26.6,-13.6) -18.7,-13.6 ; U3.9@-18.7,-15.375 -18.7,-13.6 ; v1(-16.9,-13) -18.4,-13 -18.7,-13.3 -18.7,-13.6
  Bottom Layer w0.406: v2(-1.3,-2.8) D3.3@-0.467,-2.8
PB2_5V: D4.3 SW2.1 U3.10 Z3.1 | length 28.6
  Top Layer w0.254: v1(-29.4,-18.2) -28.7,-17.5 Z3.1@-28.7,-17.2 ; v1(-13,-11.3) -12.968,-11.332 D4.3@-11.065,-11.332
  Top Layer w0.406: Z3.1@-28.7,-17.5 -28.7,-17.7 -27.64,-18.76 SW2.1@-25.51,-18.76
  Mid-Layer 1 w0.254: v1(-29.4,-18.2) -29.4,-18 -25,-13.6 v1(-17.9,-13.6) -17.9,-13 -16.2,-11.3 v1(-13,-11.3)
  Bottom Layer w0.254: U3.10@-17.9,-15.375 v1(-17.9,-13.6)
PB3_5V: D5.3 SW3.1 U3.11 Z4.1 | length 77.2
  Top Layer w0.254: v1(-2,2.2) 0.5,2.2 2.7,0 8,0 9,1 9,2.1 9.3,2.4 10.725,2.4 11.025,2.1 12.2,2.1 ; v1(13.7,-2.5) 12.2,-1 12.2,2.1 ; SW3.1@25.51,18.76 25.515,18.765 D5.3@28.568,18.765 28.568,17.568 24.5,13.5 24.5,8.4 21.2,5.1 18.943,5.1 15.943,2.1 12.2,2.1
  Mid-Layer 1 w0.254: v1(-13.1,-8.8) -13.1,-8.3 -2.6,2.2 v1(-2,2.2)
  Bottom Layer w0.254: U3.11@-17.1,-15.375 -17.1,-14.4 -14.1,-11.4 -14.1,-11 -13.1,-10 v1(-13.1,-8.8) ; Z4.1@12.8,-2.5 v1(13.7,-2.5)
PSWITCH: J4.3 J5.4 R6.2 R7.2 R8.2 | length 87.6
  Top Layer w0.381: J5.4@20.32,29.98 J5.4@20.32,30.48
  Mid-Layer 1 w0.254: J4.3@17.78,-30.48 19,-31.7 20.9,-31.7 21.5,-31.1 21.5,-2.2 22.1,-1.6 31,-1.6 31.7,-0.9 31.7,21.2 31.1,21.8 v1@27.6,21.8
  Mid-Layer 1 w0.381: J5.4@20.32,29.98 20.32,29.08 27.5,21.9 v1(27.5,21.8) ; v1@27.55,21.85 v1@27.6,21.8
  Bottom Layer w0.254: R6.2@30.5,19.2 R8.2@30.5,20.5
  Bottom Layer w0.381: v1(27.5,21.8) 28.199,22.499 R7.2@28.8,22.5 R8.2@30.5,20.8
RAS_N: U1.62 U2.23 | length 42.2
  Top Layer w0.152: v1(-20.5,15.4) -20.8,15.4 -21.3,15.9 -21.3,16.395 -20.838,16.395 -20.838,16.7 -21.3,16.7 -21.3,17.004 -20.838,17.004 -20.838,17.309 -21.3,17.309 -21.3,17.614 -20.838,17.614 -20.838,17.919 -21.3,17.919 -21.3,18.224 -20.838,18.224 -20.838,18.528 -21.3,18.528 -21.3,21.3 -20.3,22.3 -18.112,22.3 -18.108,22.297 -5.603,22.297 v1(-5.1,22.8)
  Bottom Layer w0.152: U2.23@-20.5,10.325 -20.5,11.352 -20.821,11.352 -20.821,11.657 -20.129,11.657 -20.129,11.962 -20.821,11.962 -20.821,12.267 -20.129,12.267 -20.129,12.572 -20.5,12.572 -20.5,12.876 -20.129,12.876 -20.129,13.181 -20.5,13.181 -20.5,13.486 -20.129,13.486 -20.129,13.791 -21.008,13.791 -21.008,14.096 -20.187,14.096 -20.187,14.4 -21.008,14.4 -21.008,14.705 -20.5,14.705 v1(-20.5,15.4) ; v1(-5.1,22.8) -4.5,23.4 U1.62@-2.075,23.4
RESET_N: J10.5 Q3.3 RP8.4.1 U3.29 | length 44.1
  Top Layer w0.254: v1(15.4,-24.5) Q3.3@15.4,-23.5
  Mid-Layer 1 w0.254: J10.5@-17.78,-27.94 -16.34,-26.5 14.2,-26.5 15.4,-25.3 v1(15.4,-24.5)
  Bottom Layer w0.254: J10.5@-17.78,-27.94 -16.3,-26.46 U3.29@-16.3,-23.625 ; v1(15.4,-24.5) 17.3,-24.5 17.73,-24.07 RP8.4.1@17.73,-23.462
SCK: U1.33 U5.2 | length 21.5
  Bottom Layer w0.254: U1.33@-2.075,11.8 -2.075,11.575 -1.4,10.9 -1.4,6.6 -0.184,5.384 7.916,5.384 8.65,4.65 U5.2@8.65,-0.5
SCK_5V: J10.3 U3.17 U5.4 | length 49.5
  Top Layer w0.254: J10.3@-15.24,-30.48 -12.2,-27.44 -12.2,-16 v1(-11.8,-15.6) -10.6,-15.6 -9.9,-14.9 -8.2,-14.9 -6.9,-13.6 -6.9,-11.2 v1(-5.4,-9.7)
  Bottom Layer w0.254: U3.17@-11.775,-16.7 v1@-11.775,-15.625 ; v1(-5.4,-9.7) -4.9,-9.2 -3.9,-8.2 -3.9,-6.061 -3.258,-5.419 4.381,-5.419 6.8,-3 6.8,1.1 7.7,2 U5.4@7.7,2.3
SCL: Q4.4 RP7.3.1 U1.11 | length 47.7
  Top Layer w0.254: Q4.4@18.6,-25.3 18.3,-25.3 17.9,-24.9 17.9,-22.7 19.6,-21 v1(19.6,-18.9) RP7.3.1@19.6,-17.881
  Mid-Layer 1 w0.254: v1(9.1,-4.1) 7.562,-2.562 7.562,0.116 6.9,0.778 6.9,5.222 7.577,5.9 8.1,5.9 v1(9.1,6.9)
  Bottom Layer w0.254: U1.11@7.7,10.425 7.7,9.2 9.1,7.8 v1(9.1,6.9) ; v1(9.1,-4.1) 10.238,-5.238 14.016,-5.238 15.316,-6.538 16.116,-6.538 18.662,-9.084 18.662,-14.562 19.6,-15.5 v1(19.6,-18.9)
SCL_5V: J9.3 Q4.3 RP8.3.1 U3.28 U6.6 Z2.2 | length 66.6
  Top Layer w0.254: v1(-16.2,-21.9) -16.9,-21.9 -20,-18.8 -20,-13.9 -17.1,-11 -14.772,-11 U6.6@-14.712,-10.94 ; v1(18.6,-24.5) Q4.3@18.6,-23.5
  Mid-Layer 1 w0.254: J9.3@-5.08,-30.48 -5.08,-29.38 -2.7,-27 15.1,-27 16.6,-25.5 18.2,-25.5 18.6,-25.1 v1(18.6,-24.5)
  Bottom Layer w0.254: v1(-16.2,-21.9) -16.1,-21.9 -15.5,-22.5 U3.28@-15.5,-23.625 -15.5,-25.1 -12.2,-28.4 ; v1(18.6,-24.5) 18.619,-24.481 RP8.3.1@18.619,-23.462
  Bottom Layer w0.305: -12.2,-28.4 -12.2,-31.1 -11.6,-31.7
  Bottom Layer w0.406: -11.6,-31.7 -5.63,-31.7 -5.08,-31.15 J9.3@-5.08,-30.48 -5.3,-30.26 Z2.2@-5.3,-28.805
SD_VCC: C39.1 C40.1 J1.4 J2.4 L2.1 | length 18.4
  Top Layer w0.381: J1.4@0.25,-11.5 0.25,-17.55 0.825,-18.125 J2.4@0.825,-19.45
  Top Layer w0.508: v2(0.2,-10.1) 0.2,-11.45 J1.4@0.25,-11.5
  Bottom Layer w0.508: L2.1@-1.9,-14 0.3,-14 ; v2(0.2,-10.1) 0.2,-13.9 0.3,-14 ; C40.1@2.8,-14.4 C40.1@2.6,-14.4 C39.1@0.7,-14.4 0.3,-14
SDA: Q3.1 RP7.2.1 U1.15 | length 46.4
  Top Layer w0.254: Q3.1@16.9,-23.5 16.9,-22.6 18.8,-20.7 v1(18.8,-18.9) 18.8,-17.881 RP7.2.1@18.819,-17.862
  Mid-Layer 1 w0.254: v1(8,-4.1) 7.181,-3.281 7.181,-0.042 6.481,0.658 6.481,5.342 7.419,6.281 7.681,6.281 v1(8.3,6.9)
  Bottom Layer w0.254: U1.15@6.1,10.425 6.1,8.4 7,7.5 8.1,7.5 8.3,7.3 v1(8.3,6.9) ; v1(8,-4.1) 9.519,-5.619 13.858,-5.619 15.158,-6.919 15.958,-6.919 18.281,-9.242 18.281,-14.981 18.9,-15.6 18.9,-18.8 v1(18.8,-18.9)
SDA_5V: J9.4 Q3.6 RP8.2.1 U3.27 U6.5 Z2.1 | length 61.9
  Top Layer w0.254: v1(-15.2,-21.8) -15.7,-21.3 -16.9,-21.3 -19.6,-18.6 -19.6,-14.2 -17.61,-12.21 U6.5@-14.712,-12.21 ; v1(16.9,-26.2) Q3.6@16.9,-25.3
  Mid-Layer 1 w0.254: J9.4@-2.54,-30.48 -2.54,-29.44 -0.746,-27.646 15.854,-27.646 16.9,-26.6 v1(16.9,-26.2)
  Bottom Layer w0.254: v1(-15.2,-21.8) -14.7,-22.3 U3.27@-14.7,-23.625 -14.7,-25 -12.8,-26.9 Z2.1@-5.3,-26.9 ; v1(16.9,-26.2) 18.5,-26.2 19.381,-25.319 RP8.2.1@19.381,-23.462
  Bottom Layer w0.406: Z2.1@-5.15,-26.75 -2.54,-29.36 J9.4@-2.54,-30.48
SS: Q1.1 RP5.4.1 U1.32 | length 38.8
  Top Layer w0.254: v1(12.5,3.5) 12.6,3.6 13.252,3.6 v1(14.173,4.521) ; Q1.1@22.2,1.5 22.73,2.03 RP5.4.1@24.738,2.03
  Bottom Layer w0.254: U1.32@-0.7,10.425 -0.7,8.8 -0.1,8.2 0.7,8.2 3.135,5.765 8.091,5.765 9.756,4.1 12,4.1 12.5,3.6 v1(12.5,3.5) ; v1(14.173,4.521) 14.194,4.5 14.9,4.5 16.5,2.9 16.5,-1.3 17,-1.8 21.3,-1.8 23.2,0.1 v1(23.2,2.1)
SS_5V: Q1.6 RP6.1.1 U3.32 | length 63.7
  Top Layer w0.254: v2(12.4,-24.6) 14.2,-22.8 14.2,-22.192 17,-19.392 17,-11.5 20.7,-7.8 20.7,-4.2 20.438,-3.938 RP6.1.1@19.87,-3.938 19.87,-2.83 21.1,-1.6 21.7,-1.6 22.2,-1.1 Q1.6@22.2,-0.3
  Mid-Layer 1 w0.254: v1(-18.3,-26.1) -18.1,-25.9 11.1,-25.9 v2(12.4,-24.6)
  Bottom Layer w0.254: U3.32@-18.7,-23.625 -18.7,-25.7 v1(-18.3,-26.1)
SSP1_CMD: J1.3 J2.3 RP4.3.1 U1.83 | length 57
  Top Layer w0.254: v1(4.4,7.5) 6.2,7.5 7.754,9.054 10.346,9.054 10.919,8.481 RP4.3.1@10.919,7.762
  Top Layer w0.381: v1(1.3,-7.3) 1.35,-7.35 J1.3@1.35,-11.5 1.35,-17.15 2.075,-17.875 J2.3@2.075,-19.45
  Mid-Layer 1 w0.254: v1(1.3,-7.3) 1.5,-7.1 2.2,-7.1 4.4,-4.9 4.4,-1.2 3.7,-0.5 3.7,6.8 v1(4.4,7.5) 4.8,7.9 4.8,13.2 5.654,14.054 5.654,16.329 5.2,16.783 v1(5.2,17.4)
  Bottom Layer w0.254: v1(5.2,17.4) 5.2,17.8 6.1,18.7 6.1,23.6 6.5,24 U1.83@6.5,25.575
SSP1_DAT0: J1.7 J2.7 RP1.2.1 U1.84 | length 55.5
  Top Layer w0.254: v1(6,17.8) v1@6,17.9
  Top Layer w0.381: J2.7@-3.05,-19.325 J1.7@-3.05,-11.5 -3.05,-10.15 v1(-2.7,-9.8)
  Mid-Layer 1 w0.254: v1(-2.7,-9.8) -2.7,-9.2 -2.3,-8.8 1.039,-8.8 4.781,-5.058 4.781,-1.042 4.081,-0.342 4.081,6.336 5.181,7.436 5.181,13.042 6.035,13.896 6.035,16.487 5.846,16.676 5.846,17.646 v1(6,17.8)
  Bottom Layer w0.254: J2.7@-2.925,-19.45 -2.925,-20.475 -1.481,-21.919 RP1.2.1@-1.481,-22.538 ; v1(6,17.8) 6.5,18.3 6.5,23.461 6.9,23.861 U1.84@6.9,25.575
SSP1_DAT1: J1.8 J2.8 RP1.1.1 U1.85 | length 57.4
  Top Layer w0.381: J2.8@-4.175,-19.45 -4.15,-19.425 J1.8@-4.15,-11.5 -4.15,-10.15 -3.1,-9.1 -2.1,-9.1 v1(-1.7,-9.5)
  Mid-Layer 1 w0.254: v1(-1.7,-9.5) -1.6,-9.5 -1.3,-9.2 1.178,-9.2 5.162,-5.216 5.162,-0.884 4.462,-0.184 4.462,6.178 5.562,7.278 5.562,12.884 6.416,13.738 6.416,17.084 v1(6.4,17.1)
  Bottom Layer w0.254: J2.8@-4.175,-19.45 -4.175,-21.225 -2.862,-22.538 RP1.1.1@-2.37,-22.538 ; v1(6.4,17.1) 6.9,17.6 6.9,23.322 7.3,23.722 U1.85@7.3,25.575
SSP1_DAT2: J1.1 J2.1 RP1.4.1 U1.86 | length 54.7
  Top Layer w0.381: v1(3,-9.2) 3.55,-9.75 J1.1@3.55,-11.5 3.55,-16.85 4.575,-17.875 J2.1@4.575,-19.45
  Mid-Layer 1 w0.254: v1(3,-9.2) 3.1,-9.1 3.1,-7.816 5.543,-5.373 5.543,-0.727 4.843,-0.027 4.843,6.021 5.943,7.121 5.943,12.727 6.8,13.584 6.8,16.6 7.2,17 v1(7.2,17.1)
  Bottom Layer w0.254: RP1.4.1@0.17,-22.538 2.762,-22.538 4.575,-20.725 J2.1@4.575,-19.45 ; v1@7.1,17.1 v1(7.2,17.1) ; v1@7.15,17.15 7.3,17.3 7.3,23.139 7.7,23.539 U1.86@7.7,25.575
SSP1_DAT3: J1.2 J2.2 RP1.3.1 U1.87 | length 55.6
  Top Layer w0.381: v1@2.45,-9.95 J1.2@2.45,-11.5 2.45,-16.85 3.325,-17.725 J2.2@3.325,-19.45
  Mid-Layer 1 w0.254: v1(2.5,-9.9) 3.4,-9.9 3.8,-9.5 3.8,-7.655 5.924,-5.531 5.924,-0.569 5.224,0.131 5.224,5.863 6.324,6.963 6.324,12.569 7.181,13.426 7.181,16.281 v1(8,17.1)
  Bottom Layer w0.254: RP1.3.1@-0.719,-22.538 -0.719,-21.719 -0.3,-21.3 2.8,-21.3 3.325,-20.775 J2.2@3.325,-19.45 ; v1(8,17.1) 7.7,17.4 7.7,23 8.1,23.4 U1.87@8.1,25.575
SSP1_SCK: J1.5 J2.5 U1.90 | length 53.9
  Top Layer w0.381: v1(-0.8,-9.9) -0.85,-9.95 J1.5@-0.85,-11.5 -0.85,-18.05 J2.5@-0.425,-18.475
  Mid-Layer 1 w0.254: v1(-0.8,-9.9) -0.8,-10.5 -0.4,-10.9 3.5,-10.9 4.3,-10.1 4.3,-7.694 6.305,-5.689 6.305,-0.411 5.605,0.289 5.605,5.705 6.705,6.805 6.705,12.411 7.562,13.268 7.562,16.1 8.008,16.546 8.546,16.546 v1(9.2,17.2)
  Bottom Layer w0.254: v1(9.2,17.2) 9.616,17.616 9.616,23.484 9.321,23.779 9.321,25.554 U1.90@9.3,25.575
USB_D_N: J7.2 J11.2 U1.123 | length 44
  Top Layer w0.254: v3(9.55,-14.275) 9.55,-14.478 9.881,-14.808 14.249,-14.808 J11.2@15.05,-14.008
  Mid-Layer 1 w0.254: J11.2@15.24,-13.97 15.24,-14.351 14.656,-14.935 14.224,-14.935 13.868,-14.58 13.868,-10.643 14.961,-9.55 14.961,-6.827 12.852,-4.719 12.852,-1.936 15.9,1.112 15.9,8.938 15.6,9.239 v1(15.6,9.9)
  Bottom Layer w0.254: J7.2@7.7,-13.7 8,-14 9.276,-14 v3(9.55,-14.275) ; U1.123@13.075,13.8 14.639,13.8 15.672,12.767 15.672,9.972 v1(15.6,9.9) ; J11.2@15.05,-14.008 15.24,-14.199 J11.2@15.24,-13.97
USB_D_P: J7.3 J11.3 U1.124 | length 44
  Top Layer w0.254: v3(9.525,-15.392) 9.728,-15.392 9.931,-15.189 14.036,-15.189 14.874,-16.027 J11.3@15.24,-16.027
  Mid-Layer 1 w0.254: v1(14.9,9.4) 15.519,8.781 15.519,1.27 12.471,-1.778 12.471,-4.877 14.58,-6.985 14.58,-9.373 13.487,-10.465 13.487,-14.757 J11.3@15.24,-16.51
  Bottom Layer w0.254: J7.3@7.7,-15.7 9.217,-15.7 v3(9.525,-15.392) ; U1.124@13.075,13.4 14.5,13.4 15.291,12.609 15.291,10.389 14.9,9.998 v1(14.9,9.4) ; J11.3@15.24,-16.51 J11.3@15.24,-16.027
VBAT: C18.1 C19.1 C20.1 D1.1 J5.1 U1.100 U1.103 | length 24.3
  Top Layer w0.508: C20.1@10,19.25 C19.1@10,21.25 ; C18.1@10,23.25 10,22.5 ; 11.25,21.25 C19.1@10,21.25 ; v1@11.25,22.5 10,22.5 ; C19.1@10,21.25 10,22.5
  Top Layer w0.61: 12.7,28.4 14.8,28.4 v2@16.05,27.15
  Top Layer w0.762: C18.1@10,23.25 10,25.7 12.7,28.4 J5.1@12.7,30.48
  Bottom Layer w0.254: 11.5,21.8 U1.103@13.075,21.8 ; v1@11.5,22.4 v1(11.521,22.421) 12.1,23 U1.100@13.075,23
  Bottom Layer w0.508: 11.5,21.8 v1@11.5,22.4
  Bottom Layer w0.61: v2(16.2,26.9) 16.2,26.3 16.7,25.8 D1.1@16.95,25.8
  other v1: 11.5,21.5
VDD4P2: C8.1 C9.1 D1.2 U1.101 | length 16.4
  Top Layer w0.508: 16.5,25.3 16.5,25.7
  Top Layer w0.61: C8.1@13,21.75 13.75,22.5 v1(14.8,22.5) 14.8,24 16.5,25.7 C9.1@17.7,25.7 ; 16.5,25.3 17.2,24.6 20.5,24.6 v2(21.7,25.8)
  Bottom Layer w0.254: U1.101@13.075,22.6 14.7,22.6 v1(14.8,22.5)
  Bottom Layer w0.508: D1.2@20.65,25.8 v2(21.7,25.8)
VDDA: C16.1 C17.1 C38.1 U1.96 U1.110 | length 17.2
  Top Layer w0.61: C38.1@13.1,18.7 13.7,19.3 v1(14.5,19.3)
  Mid-Layer 1 w0.381: v1(12.4,25.2) 13.1,24.5 13.1,20.7 v1(14.5,19.3)
  Bottom Layer w0.254: 11.7,28.7 U1.96@11.7,25.575 12.025,25.575 v1(12.4,25.2) ; U1.110@13.075,19 14.2,19 v1(14.5,19.3)
  Bottom Layer w0.305: C17.1@10.3,29.1 11.3,29.1 11.7,28.7
  Bottom Layer w0.406: C16.1@8.6,29.2 C17.1@10.3,29.2
VDDD: C1.1 C2.1 C11.1 C12.1 U1.1 U1.93 U1.94 | length 29
  Top Layer w0.254: C1.1@9.9,13.3 C1.1@10,13.4 ; v1(10,12.5) v1@10,12.6
  Top Layer w0.406: C2.1@6.9,29.2 C11.1@8.6,29.2 C12.1@10.3,29.2 10.5,29 v1(10.5,27.5)
  Top Layer w0.508: v1@10,12.6 C1.1@10,13.4
  Mid-Layer 1 w0.381: v1(10,12.5) 10,12.6 10.6,13.2 10.6,17.4 10.383,17.617 10.383,27.383 v1(10.5,27.5)
  Bottom Layer w0.254: v1(10,12.5) 10,12.6 10.1,12.7 10.6,12.7 11.7,11.6 U1.1@11.7,10.425 ; U1.93@10.5,25.575 10.5,26.7 v1(10.5,27.5) ; v1@10.6,27.4 10.9,27.1 U1.94@10.9,25.575
VDDXTAL: C31.1 J5.3 U1.120 | length 21.1
  Top Layer w0.254: v1(16.3,15) C31.1@17.5,15
  Mid-Layer 1 w0.254: v1(16.3,15) 16.7,15 18.2,16.5 18.2,30.06 J5.3@17.78,30.48
  Bottom Layer w0.254: U1.120@13.075,15 v1(16.3,15)
WE_N: U1.77 U2.21 | length 42.2
  Top Layer w0.152: v1(-19.2,13.1) -20.811,14.711 -21.047,14.476 -21.262,14.691 -21.027,14.927 -21.579,15.479 -21.579,21.425 -20.384,22.621 -18.784,22.621 -18.403,23.002 -18.403,23.008 -18.108,23.303 -17.692,23.303 -17.688,23.3 -15.512,23.3 -15.508,23.303 -15.092,23.303 -15.088,23.3 -13.562,23.3 -13.558,23.303 -13.142,23.303 -13.138,23.3 -11.612,23.3 -11.608,23.303 -11.192,23.303 -11.188,23.3 -9.662,23.3 -9.658,23.303 -9.242,23.303 -9.238,23.3 -7.712,23.3 -7.708,23.303 -7.292,23.303 -7.288,23.3 -6.412,23.3 -6.408,23.303 -5.992,23.303 -5.988,23.3 -5.312,23.3 -5.308,23.303 -4.892,23.303 -4.888,23.3 -4.112,23.3 -4.108,23.303 -3.692,23.303 -3.688,23.3 -2.3,23.3 1.6,27.2 v1(3.6,27.2)
  Bottom Layer w0.152: U2.21@-19.2,10.325 v1(-19.2,13.1) ; v1(3.6,27.2) 4.1,26.7 U1.77@4.1,25.575
pads on no net: D2.2 D3.2 D4.2 D5.2 D6.2 J1.G4 J6.0 LED2.4 LED3.1 LED3.4 SW1.2 SW2.2 SW3.2 U1.6 U1.7 U1.8 U1.9 U1.12 U1.16 U1.17 U1.104 U1.109 U1.111 U1.113 U1.114 U1.115 U1.116 U2.14 U2.17 U2.19 U2.25 U2.43 U2.50 U2.53 U3.13 U3.19 U3.22 U4.1 U5.1
copper on no net:
  other v1: -22.5,-30 -22.5,-27.5 -27.5,-10 -30,-2.5 -27.5,-2.5 -25,-2.5 -30,15 -27.5,17.5 -30,22.5 -22.5,30 22.5,30

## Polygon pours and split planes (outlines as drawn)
GND on Top Layer "Top Layer-GND" (solid, remove dead copper, pour order 5): -33.5,-33.5 -33.5,33.5 33.5,33.5 33.5,-33.5
GND on Mid-Layer 1 "Mid Layer-GND" (solid, remove dead copper, pour order 7): -33.5,-33.5 -33.5,33.5 33.5,33.5 33.5,-33.5
GND on Bottom Layer "Bottom Layer-GND" (solid, remove dead copper, pour order 9): -33.5,-33.5 -33.5,33.5 33.5,33.5 33.5,-33.5
GND on InternalPlane1 (split plane): 32.99,-3.1 23.1,-3.1 23.1,-32.99 -32.99,-32.99 -32.99,32.99 32.99,32.99

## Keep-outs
Top Layer:
  rectangle: 23.1,-33.5 33.5,-3.1
Mid-Layer 1:
  rectangle: 23.1,-33.5 33.5,-3.1
Bottom Layer:
  rectangle: 23.1,-33.5 33.5,-3.1
Keep-Out Layer:
  the board outline again, w0.9

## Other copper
InternalPlane1 (plane layer: these items are gaps in the copper):
  rectangle: 23.1,-33.5 33.5,-3.1

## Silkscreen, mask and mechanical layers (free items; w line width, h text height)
Top Overlay:
  drawing of 1968 lines, arcs and shapes, not listed
  text "MooresCloud" at -25,16.5 h2.54
  text "Holiday r1" at -23.4,12.4 h2.54
  text "Kean - May 2013" at -29,-8 h2 r90
  text "Hack Me!" at -5.6,-28 h1.52
Bottom Overlay:
  drawing of 808 lines, arcs and shapes, not listed
Mechanical 1:
  lines w0.254: -33.6,-33.5 33.4,-33.5 33.4,33.5 -33.6,33.5 -33.6,-33.5
Mechanical 2:
  circle w0.254: c0,0 r8.7
  circle w0.254: c0,0 r6
  region: 13.3,12.5 11.5,14.4 15.6,18.5 17.5,16.7
  region: -15,-33.5 15,-33.5 9.7,-13 6.2,-13 6.2,-16 -6.2,-16 -6.2,-13 -9.7,-13
  region: -13.3,-12.5 -11.5,-14.4 -15.6,-18.5 -17.5,-16.7
  region: 15,-19 13,-17 17,-13 19,-15
  region: -15,19 -13,17 -17,13 -19,15
  region: 26.4,31.4 28.4,31.4 28.4,28.4 31.4,28.4 31.4,26.4 28.4,26.4 28.4,23.4 26.4,23.4 26.4,26.4 23.4,26.4 23.4,28.4 26.4,28.4
  region: 26.4,-23.4 28.4,-23.4 28.4,-26.4 31.4,-26.4 31.4,-28.4 28.4,-28.4 28.4,-31.4 26.4,-31.4 26.4,-28.4 23.4,-28.4 23.4,-26.4 26.4,-26.4
  region: -28.4,-23.4 -26.4,-23.4 -26.4,-26.4 -23.4,-26.4 -23.4,-28.4 -26.4,-28.4 -26.4,-31.4 -28.4,-31.4 -28.4,-28.4 -31.4,-28.4 -31.4,-26.4 -28.4,-26.4
  region: -28.4,31.4 -26.4,31.4 -26.4,28.4 -23.4,28.4 -23.4,26.4 -26.4,26.4 -26.4,23.4 -28.4,23.4 -28.4,26.4 -31.4,26.4 -31.4,28.4 -28.4,28.4
  region: -33.5,33.5 -23.5,33.5 -33.5,23.5
  region: 33.5,33.5 33.5,23.5 23.5,33.5
  region: 33.5,-33.5 23.5,-33.5 33.5,-23.5
  region: -33.5,-33.5 -33.5,-23.5 -23.5,-33.5
  text "Top Layer Component Keep Out Areas" at 45,-26.2 h1
  text "Top Layer Component Keep Out Areas" at 109.1,-58.3 h1
Mechanical 3:
  circle w0.254: c27.4,-27.4 r4.4
  circle w0.254: c-27.4,-27.4 r4.4
  circle w0.254: c-27.4,27.4 r4.4
  circle w0.254: c27.4,27.4 r4.4
  rectangle: -3.5,6 3.5,8
  rectangle: -3.5,-8 3.5,-6
  text "Bottom Layer Component Keep Out Areas" at 45,-28.2 h1
  text "Bottom Layer Component Keep Out Areas" at 109.1,-60.3 h1
Drill Drawing:
  lines w0.1: 44.5,-33.3 102.75,-33.3 ; 44.5,-31.3 102.75,-31.3 ; 44.5,-22.55 102.75,-22.55 ; 44.5,-20.55 102.75,-20.55 ; 44.5,-18.55 102.75,-18.55 ; 44.5,-16.55 102.75,-16.55 ; 44.5,-14.55 102.75,-14.55 ; 44.5,-12.55 102.75,-12.55 ; 44.5,-10.55 102.75,-10.55 ; 44.5,-8.55 102.75,-8.55 ; 57,-35.3 57,-29.05 ; 57,-24.55 57,-6.55 ; -33.5,-33.5 -33.5,33.5 33.5,33.5 33.5,-33.5 -33.5,-33.5 ; 44.5,-35.3 44.5,-29.05 102.75,-29.05 102.75,-35.3 44.5,-35.3 ; 44.5,-24.55 102.75,-24.55 102.75,-6.55 44.5,-6.55 44.5,-24.55
  lines w0.15: 45.524,44.6 100.576,44.6 ; 45.524,47.415 100.576,47.415 ; 44,26.9 ccw(c44.9,26.9) 44.9,26 101.2,26 ccw(c101.2,26.9) 102.1,26.9 102.1,49.8 ccw(c101.2,49.8) 101.2,50.7 44.9,50.7 ccw(c44.9,49.8) 44,49.8 44,26.9
  text "Layer Stack Up Detail for: Holiday r1.PcbDoc" at 45.524,48.173 h1.2
  text "Layer" at 45.524,46.365 h0.65
  text "Gerber" at 71.095,46.365 h0.65
  text "Dielectric" at 88.022,46.365 h0.65
  text "Name" at 45.524,45.065 h0.65
  text "Document" at 71.095,45.065 h0.65
  text "Material" at 88.022,45.065 h0.65
  text "Top Solder Mask" at 45.524,43.239 h0.9
  text "(.GTS)" at 71.095,43.239 h0.9
  text "Solder Resist" at 88.022,43.239 h0.9
  text "Top Layer" at 45.524,40.666 h0.9
  text "(.GTL)" at 71.095,40.666 h0.9
  text "FR-4" at 88.022,39.379 h0.9
  text "Mid-Layer 1" at 45.524,38.093 h0.9
  text "(.G1)" at 71.095,38.093 h0.9
  text "FR-4" at 88.022,36.806 h0.9
  text "InternalPlane1" at 45.524,35.52 h0.9
  text "(.GP1)" at 71.095,35.52 h0.9
  text "FR-4" at 88.022,34.233 h0.9
  text "Bottom Layer" at 45.524,32.947 h0.9
  text "(.GBL)" at 71.095,32.947 h0.9
  text "Bottom Solder Mask" at 45.524,30.374 h0.9
  text "(.GBS)" at 71.095,30.374 h0.9
  text "Solder Resist" at 88.022,30.374 h0.9
  text ".legend" at 45.75,-1.3 h1
  text "BOARD SIZE:" at 45,-8.05 h1
  text "67.00mm x 67.00mm" at 58,-8.05 h1
  text "LAYERS:" at 45,-10.05 h1
  text "4" at 58,-10.05 h1
  text "MATERIAL:" at 45,-12.05 h1
  text "FR4 1.6mm" at 58,-12.05 h1
  text "COPPER:" at 45,-14.05 h1
  text "35um (after plating)" at 58,-14.05 h1
  text "PTH PLATING:" at 45,-16.05 h1
  text "20um (minimum)" at 58,-16.05 h1
  text "FINISH:" at 45,-18.05 h1
  text "ROHS ENIG or HAL ?" at 58,-18.05 h1
  text "OVERLAY:" at 45,-20.05 h1
  text "White, 2 sides" at 58,-20.05 h1
  text "SOLDER MASK:" at 45,-22.05 h1
  text "Green LPI, 2 sides" at 58,-22.05 h1
  text "PROFILING:" at 45,-24.05 h1
  text "V-Groove" at 58,-24.05 h1
  text "FILE NAME:" at 45,-30.8 h1
  text ".Pcb_File_Name_No_Path" at 58,-30.8 h1
  text "LAYER:" at 45,-32.8 h1
  text ".Plot_File_Name" at 58,-32.8 h1
  text "PRINT DATE:" at 45,-34.8 h1
  text ".Print_Date" at 58,-34.8 h1

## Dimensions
-33.5,-33.5 to 33.5,-33.5 on Drill Drawing
-33.5,-33.5 to -33.5,33.5 on Drill Drawing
